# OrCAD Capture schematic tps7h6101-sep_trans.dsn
size Custom
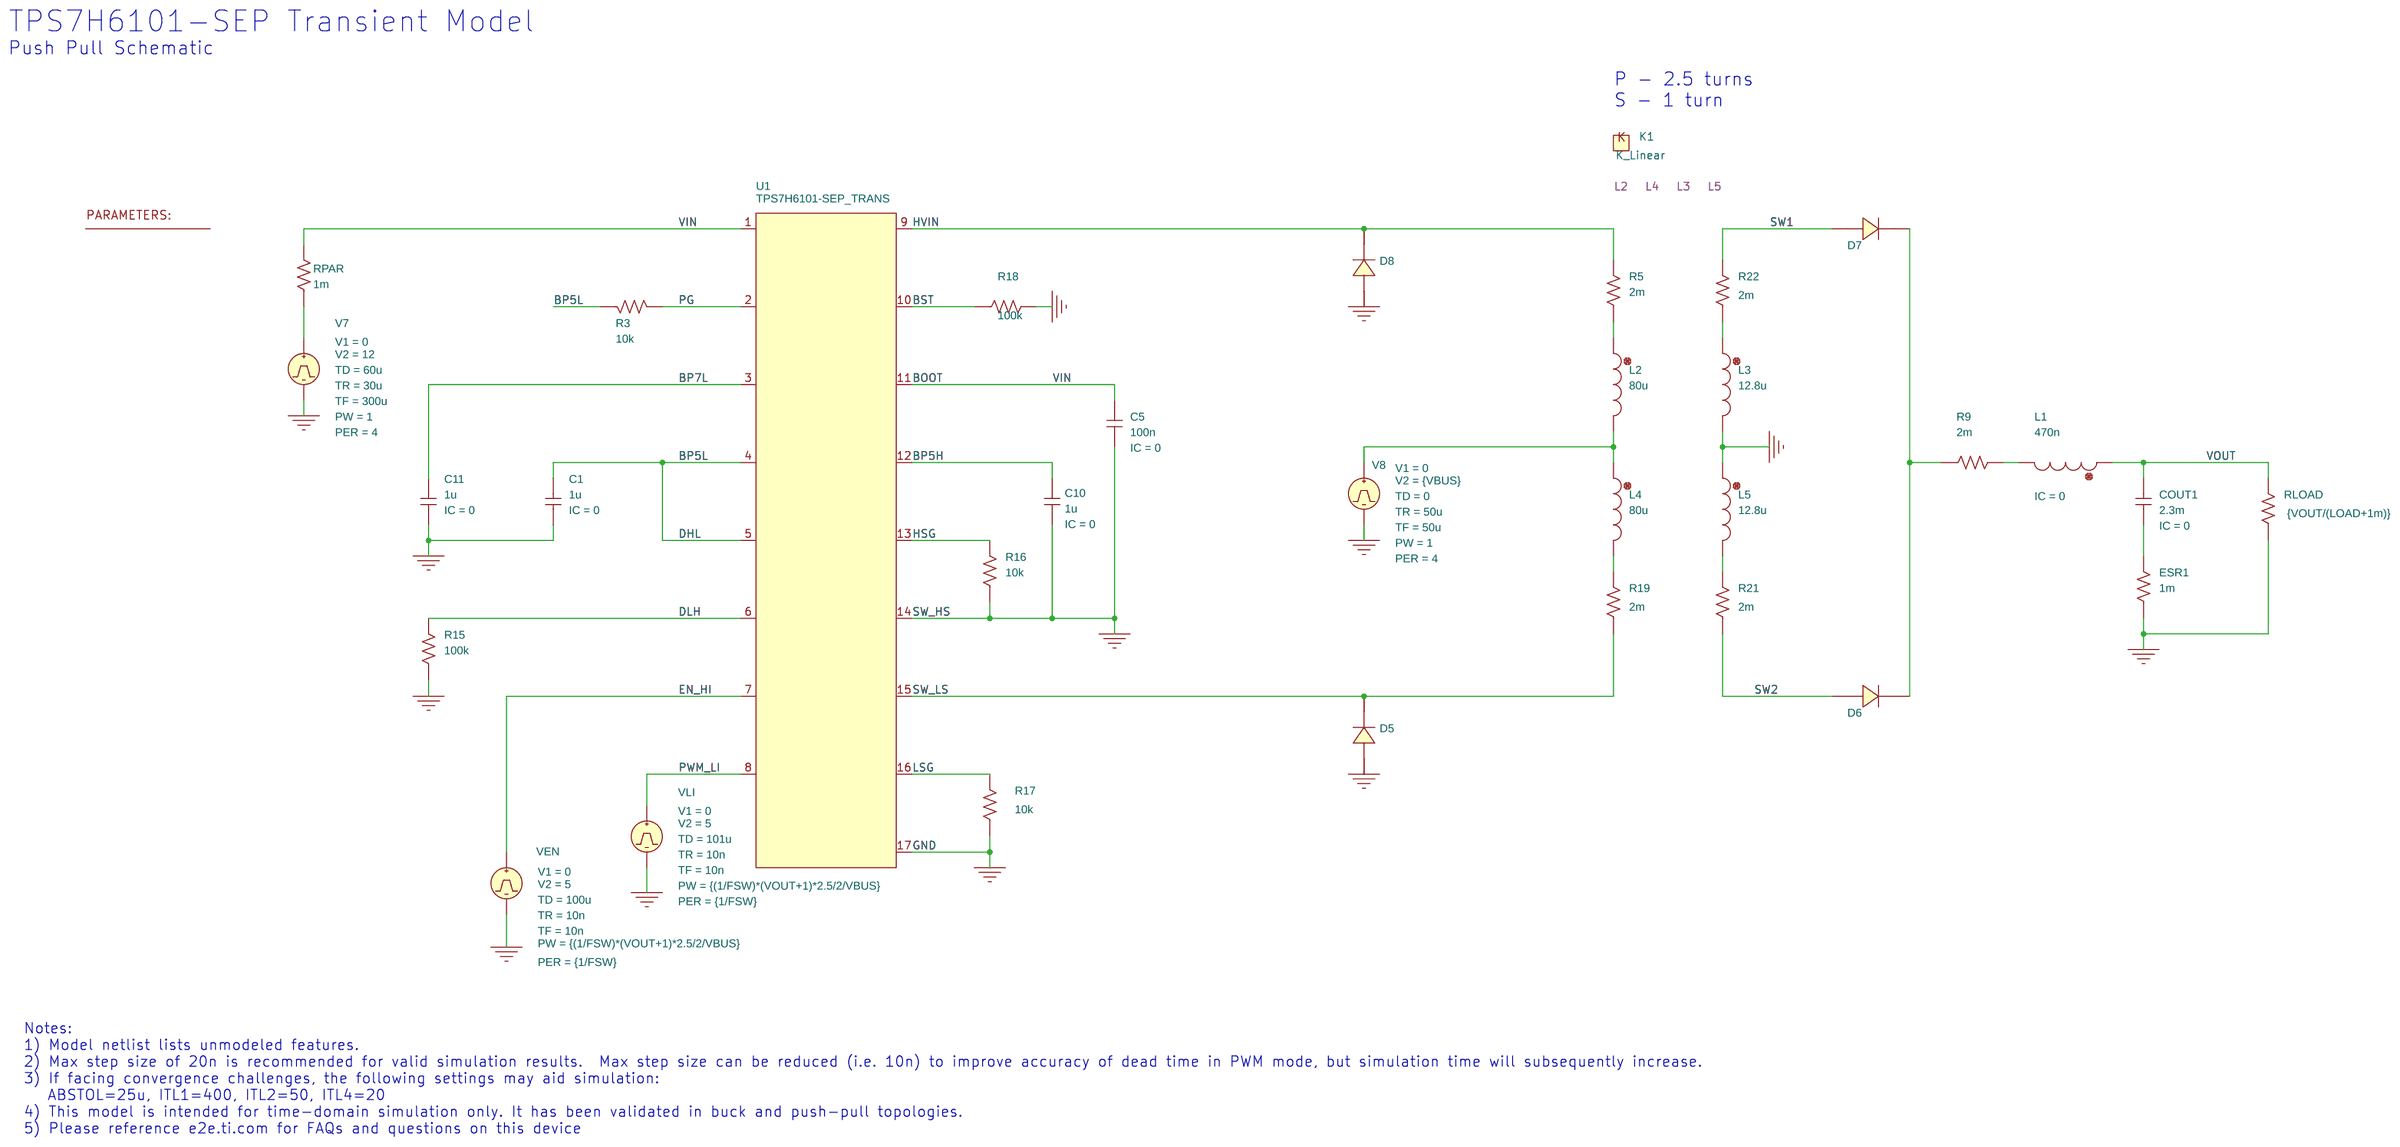
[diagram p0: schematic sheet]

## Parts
1  PARAM
C1  1u  [cap196]
C5  100n  [cap196]
C10  1u  [cap196]
C11  1u  [cap196]
COUT1  2.3m  [cap196]
D5  D_D1  [DO41]
D6  D_D1  [DO41]
D7  D_D1  [DO41]
D8  D_D1  [DO41]
ESR1  1m  [AXRC05]
K1  K_Linear
L1  470n  [DISC350x175LS200x100034]
L2  80u  [DISC350x175LS200x100034]
L3  12.8u  [DISC350x175LS200x100034]
L4  80u  [DISC350x175LS200x100034]
L5  12.8u  [DISC350x175LS200x100034]
R3  10k  [AXRC05]
R5  2m  [AXRC05]
R9  2m  [AXRC05]
R15  100k  [AXRC05]
R16  10k  [AXRC05]
R17  10k  [AXRC05]
R18  100k  [AXRC05]
R19  2m  [AXRC05]
R21  2m  [AXRC05]
R22  2m  [AXRC05]
RLOAD  {VOUT/(LOAD+1m)}  [AXRC05]
RPAR  1m  [AXRC05]
U1  TPS7H6101-SEP_TRANS
V7  VPULSE
V8  VPULSE
VEN  VPULSE
VLI  VPULSE

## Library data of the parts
1 = PARAM: FSW: 500k; LOAD: 5; VBUS: 28; VOUT: 5
C1 C5 C10 C11 COUT1 = C: IC: 0
D5-D8 = D_D1
ESR1 R3 R5 R9 R15-R19 R21 R22 RLOAD RPAR = R
K1 = K_Linear: COUPLING: 0.99; L1: L2; L2: L4; L3: L3; L4: L5
L1 = L: IC: 0
L2-L5 = L
U1 = TPS7H6101-SEP_TRANS
V7 = VPULSE: PER: 4; PW: 1; TD: 60u; TF: 300u; TR: 30u; V1: 0; V2: 12
V8 = VPULSE: PER: 4; PW: 1; TD: 0; TF: 50u; TR: 50u; V1: 0; V2: {VBUS}
VEN = VPULSE: PER: {1/FSW}; PW: {(1/FSW)*(VOUT+1)*2.5/2/VBUS}; TD: 100u; TF: 10n; TR: 10n; V1: 0; V2: 5
VLI = VPULSE: PER: {1/FSW}; PW: {(1/FSW)*(VOUT+1)*2.5/2/VBUS}; TD: 101u; TF: 10n; TR: 10n; V1: 0; V2: 5

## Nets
0: C1.1 C5.1 C10.1 C11.1 D5.2(A) D8.2(A) ESR1.1 L3.2 L5.1 R15.1 R16.1 R17.1 R18.2 RLOAD.1 U1.14(SW_HS) U1.17(GND) V7.2(-) V8.2(-) VEN.2(-) VLI.2(-)
BOOT: C5.2 RPAR.2 U1.1(VIN) U1.11(BOOT)
BP5H: C10.2 U1.12(BP5H)
BP5L: C1.2 R3.1 U1.4(BP5L) U1.5(DHL)
BP7L: C11.2 U1.3(BP7L)
BST: R18.1 U1.10(BST)
DLH: R15.2 U1.6(DLH)
EN_HI: U1.7(EN_HI) VEN.1(+)
HSG: R16.2 U1.13(HSG)
HVIN: D8.1(C) R5.2 U1.9(HVIN)
LSG: R17.2 U1.16(LSG)
PG: R3.2 U1.2(PGOOD)
PWM_LI: U1.8(PWM_LI) VLI.1(+)
SW1: D7.2(A) R22.2
SW2: D6.2(A) R21.1
SW_LS: D5.1(C) R19.1 U1.15(SW_LS)
VOUT: COUT1.2 L1.1 RLOAD.2
N107672: RPAR.1 V7.1(+)
N107824: D6.1(C) D7.1(C) R9.1
N107830: L1.2 R9.2
N108202: COUT1.1 ESR1.2
N110940: L2.2 L4.1 V8.1(+)
N111259: L2.1 R5.1
N122306: L5.2 R21.2
N122382: L3.1 R22.1
N123240: L4.2 R19.2

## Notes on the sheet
- TPS7H6101-SEP Transient Model
- Push Pull Schematic
- P - 2.5 turns
  S - 1 turn
- Notes:
  1) Model netlist lists unmodeled features.
  2) Max step size of 20n is recommended for valid simulation results.  Max step size can be reduced (i.e. 10n) to improve accuracy of dead time in PWM mode, but simulation time will subsequently increase.
  3) If facing convergence challenges, the following settings may aid simulation:
     ABSTOL=25u, ITL1=400, ITL2=50, ITL4=20
  4) This model is intended for time-domain simulation only. It has been validated in buck and push-pull topologies.
  5) Please reference e2e.ti.com for FAQs and questions on this device
